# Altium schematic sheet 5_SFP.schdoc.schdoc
size 431 x 309 mm; Symbol: Sheet-Symbol_A3; Device: Sheet-Symbol_A3; Company: 嘉立创EDA; Version: V1.0; Page Size: A3; @Project Name: RTL8367S_RTL8213B; @Page Count: 5; @Update Date: 2022-11-25; @Create Date: 2022-10-17; @Schematic Name: Schematic1; @Page No: 5; @Page Name: SFP
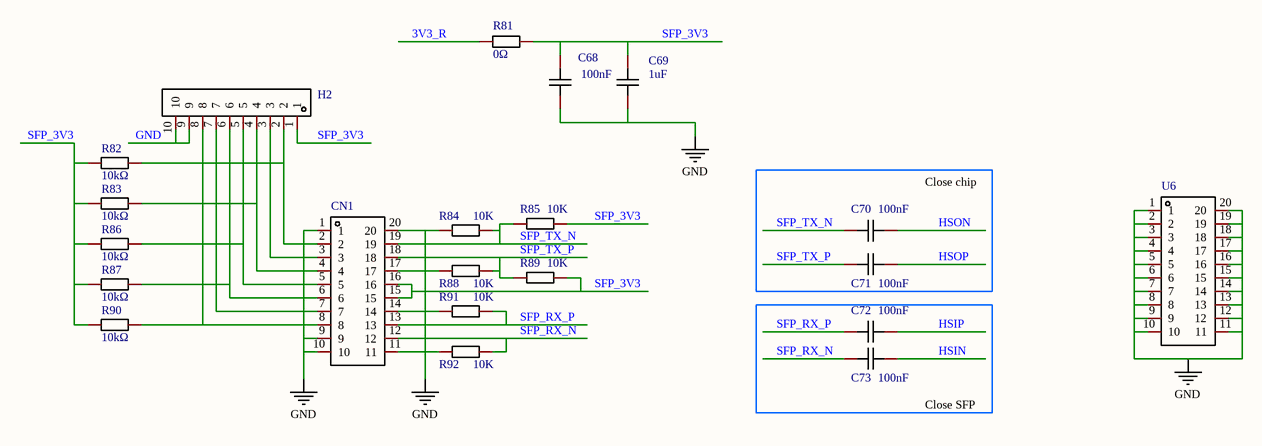
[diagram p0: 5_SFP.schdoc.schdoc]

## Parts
C68  value 100nF  [C0402_NEW]  (hidden comment: CL05B104KO5NNNC)
C69  value 1uF  [C0603]  (hidden comment: CL10A105KB8NNNC)
C70  value 100nF  [C0402_NEW]  (hidden comment: CL05B104KO5NNNC)
C71  value 100nF  [C0402_NEW]  (hidden comment: CL05B104KO5NNNC)
C72  value 100nF  [C0402_NEW]  (hidden comment: CL05B104KO5NNNC)
C73  value 100nF  [C0402_NEW]  (hidden comment: CL05B104KO5NNNC)
CN1  1367073-1  [SFP-SMD_1367073-1]  (value not drawn)
H2  HDR-F_2.54_1x10P  [HDR-TH_10P-P2.54-V-F]  (value not drawn)
R81  value 0Ω  [R0603]  (hidden comment: 0603WAF0000T5E)
R82  value 10kΩ  [R0402]  (hidden comment: 0402WGF1002TCE)
R83  value 10kΩ  [R0402]  (hidden comment: 0402WGF1002TCE)
R84  value 10K  [R0402]  (hidden comment: Res_0402)
R85  value 10K  [R0402]  (hidden comment: Res_0402)
R86  value 10kΩ  [R0402]  (hidden comment: 0402WGF1002TCE)
R87  value 10kΩ  [R0402]  (hidden comment: 0402WGF1002TCE)
R88  value 10K  [R0402]  (hidden comment: Res_0402)
R89  value 10K  [R0402]  (hidden comment: Res_0402)
R90  value 10kΩ  [R0402]  (hidden comment: 0402WGF1002TCE)
R91  value 10K  [R0402]  (hidden comment: Res_0402)
R92  value 10K  [R0402]  (hidden comment: Res_0402)
U6  HC-SFP-01L  [TH_HC-SFP-01L]  (value not drawn)

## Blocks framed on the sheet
Close chip: C70 C71
Close SFP: C72 C73

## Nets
GND: C68.1 C69.1 CN1.1 CN1.9 CN1.10 CN1.11 CN1.14 CN1.17 CN1.20 H2.9 H2.10 R84.1 R88.1 R91.1 R92.1 U6.1 U6.2 U6.3 U6.4 U6.5 U6.6 U6.7 U6.8 U6.9 U6.10 U6.11 U6.12 U6.13 U6.14 U6.15 U6.16 U6.17 U6.18 U6.19 U6.20
3V3_R: R81.1
HSIN: C73.2
HSIP: C72.2
HSON: C70.2
HSOP: C71.2
SFP_3V3: C68.2 C69.2 CN1.15 CN1.16 H2.1 R81.2 R82.2 R83.2 R85.2 R86.2 R87.2 R89.2 R90.2
SFP_RX_N: C73.1 CN1.12 R92.2
SFP_RX_P: C72.1 CN1.13 R91.2
SFP_TX_N: C70.1 CN1.19 R84.2 R85.1
SFP_TX_P: C71.1 CN1.18 R88.2 R89.1
NetCN1_2: CN1.2 H2.2 R82.1
NetCN1_3: CN1.3 H2.3
NetCN1_4: CN1.4 H2.4 R83.1
NetCN1_5: CN1.5 H2.5 R86.1
NetCN1_6: CN1.6 H2.6 R87.1
NetCN1_7: CN1.7 H2.7
NetCN1_8: CN1.8 H2.8 R90.1

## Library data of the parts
C68 C70-C73 = CL05B104KO5NNNC: Manufacturer: SAMSUNG(三星); Symbol: C1210X7R475K630NT; Add into BOM: yes; Tolerance: ±10%; Voltage Rated: 16V; Temperature Coefficient: X7R; Description: 容值:100nF;精度:±10%;额定电压:16V;材质(温度系数):X7R;
C69 = CL10A105KB8NNNC: Manufacturer: SAMSUNG(三星); Symbol: C1210X7R475K630NT; Add into BOM: yes; Tolerance: ±10%; Voltage Rated: 50V; Temperature Coefficient: X5R; Description: 容值:1uF;精度:±10%;额定电压:50V;材质(温度系数):X5R;
CN1 = 1367073-1: Manufacturer: TE Connectivity(美国泰科); Add into BOM: yes; Connector Type: SFP; Pitch: 0.8mm; Description: 连接器类型:SFP;间距:0.8mm;引脚总数:20;安装方式:卧贴;工作温度范围:-;
H2 = HDR-F_2.54_1x10P: Symbol: X5511FV-10-C70D30-1000; Add into BOM: no; Convert to PCB: yes
R81 = 0603WAF0000T5E: Manufacturer: UNI-ROYAL(厚声); Symbol: 电阻; Add into BOM: yes; Tolerance: ±1%; Power(Watts): 1/10W; Overload Voltage (Max): 75V; Description: 温度系数:-;精度:±1%;阻值:0Ω;功率:1/10W;最大工作电压:75V;工作温度范围:-55℃~+155℃;
R82 R83 R86 R87 R90 = 0402WGF1002TCE: Manufacturer: UNI-ROYAL(厚声); Symbol: 电阻; Add into BOM: yes; Tolerance: ±1%; Power(Watts): 62.5mW; Temperature Coefficient: ±100ppm/℃; Overload Voltage (Max): 50V; Description: 电阻类型:厚膜电阻;阻值:10kΩ;精度:±1%;功率:62.5mW;温度系数:±100ppm/℃;最大工作电压:50V;工作温度范围:-55℃~+155℃;
R84 R85 R88 R89 R91 R92 = Res_0402: Symbol: 电阻; Convert to PCB: yes; Add into BOM: no
U6 = HC-SFP-01L: Manufacturer: HCTL(华灿天禄); Add into BOM: no; Convert to PCB: yes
